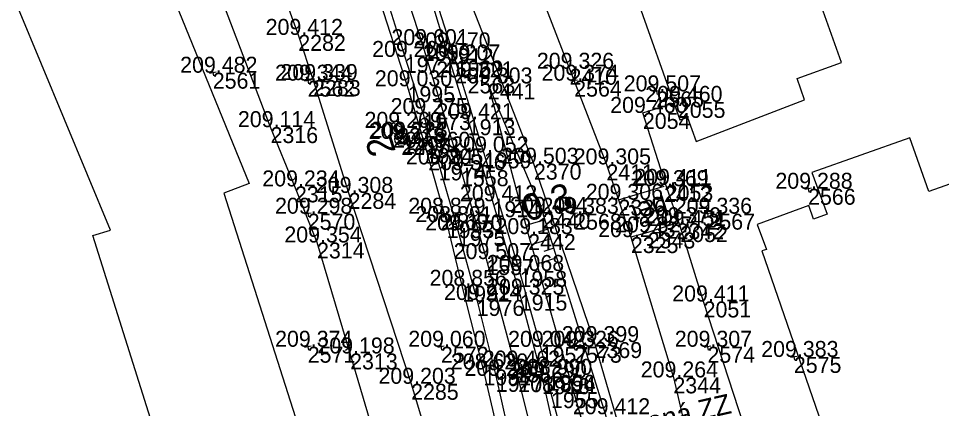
# Model space of a CAD drawing. Extents: x -556590 to -554855, y -1137918 to -1135717.
# Drawn here: x -555011.7 to -554942.4, y -1137304.6 to -1137275.3 of the extents above; entities that cross this region are included whole.
import ezdxf

# ---------------------------------------------------------------- set-up
doc = ezdxf.new("R2010")
doc.units = 0
for name, color, linetype in [('Vrstva 1', 7, 'Continuous'), ('Vrstva 11', 7, 'Continuous'), ('Vrstva 17', 7, 'Continuous'), ('Vrstva 23', 7, 'Continuous'), ('Vrstva 4', 7, 'Continuous'), ('Vrstva 48', 7, 'Continuous'), ('Vrstva 49', 7, 'Continuous'), ('Vrstva 50', 7, 'Continuous'), ('Vrstva 51', 7, 'Continuous'), ('Vrstva 60', 7, 'Continuous'), ('Vrstva 61', 7, 'Continuous'), ('Vrstva 7', 7, 'Continuous')]:
    doc.layers.add(name, color=color, linetype=linetype)

msp = doc.modelspace()

# ---------------------------------------------------------------- linework, layer by layer
at = {"layer": 'Vrstva 1'}
msp.add_lwpolyline([(-554957.769, -1137391.473), (-554957.969, -1137390.265), (-554958.079, -1137389.516), (-554959.228, -1137381.711), (-554960.83, -1137371.074), (-554962.414, -1137360.882), (-554964.146, -1137350.305), (-554965.833, -1137340.679), (-554967.766, -1137330.506), (-554969.82, -1137320.65), (-554972.001, -1137311.137), (-554974.412, -1137301.49), (-554976.593, -1137293.41), (-554978.496, -1137286.733), (-554981.36, -1137277.327), (-554984.2, -1137268.613)], dxfattribs=at)
at = {"layer": 'Vrstva 11'}
for p, q in [((-554982.974, -1137283.935), (-554983.78, -1137283.506)), ((-554982.791, -1137283.608), (-554983.609, -1137283.172)), ((-554983.466, -1137284.318), (-554982.648, -1137284.754)), ((-554983.283, -1137283.991), (-554982.477, -1137284.42))]:
    msp.add_line(p, q, dxfattribs=at)
for centre in [(-554983.284, -1137283.548), (-554982.973, -1137284.378)]:
    msp.add_circle(centre, 0.5, dxfattribs=at)
at = {"layer": 'Vrstva 17'}
msp.add_lwpolyline([(-554954.655, -1137315.2), (-554957.273, -1137305.896), (-554960.287, -1137296.596), (-554962.039, -1137290.931), (-554963.134, -1137287.835), (-554964.847, -1137282.426), (-554962.218, -1137281.595)], dxfattribs=at)
at = {"layer": 'Vrstva 23'}
for points in [[(-554974.008, -1137234.741), (-554973.079, -1137238.66), (-554969.088, -1137237.709), (-554968.749, -1137239.093), (-554976.722, -1137241.899), (-554973.235, -1137251.876), (-554974.414, -1137252.257), (-554966.688, -1137273.494), (-554965.541, -1137273.087), (-554962.076, -1137282.947), (-554961.502, -1137282.771), (-554960.834, -1137284.579), (-554952.711, -1137281.431), (-554953.254, -1137279.845), (-554949.927, -1137278.646), (-554953.433, -1137268.78), (-554952.345, -1137268.415), (-554960.023, -1137247.127), (-554960.935, -1137247.503), (-554964.348, -1137238.407), (-554963.788, -1137238.208), (-554965.053, -1137232.957), (-554974.008, -1137234.741)], [(-555001.443, -1137270.389), (-554994.396, -1137287.723), (-554996.287, -1137288.452), (-554990.752, -1137305.874), (-554993.395, -1137306.708), (-554992.699, -1137309.185), (-554997.164, -1137310.589), (-554997.913, -1137308.185), (-555000.641, -1137309.05), (-555006.14, -1137291.642), (-555004.803, -1137291.24), (-555011.71, -1137274.605), (-555001.443, -1137270.389)], [(-554956.269, -1137290.801), (-554955.577, -1137292.686), (-554955.907, -1137292.801), (-554949.985, -1137309.973), (-554932.082, -1137303.548), (-554938.146, -1137286.479), (-554943.374, -1137288.342), (-554944.804, -1137284.29), (-554952.158, -1137286.912), (-554951.004, -1137290.033), (-554952.049, -1137290.402), (-554952.396, -1137289.39), (-554956.269, -1137290.801)]]:
    msp.add_lwpolyline(points, dxfattribs=at)
at = {"layer": 'Vrstva 4'}
for points in [[(-554984.585, -1137272.161), (-554982.714, -1137278.214), (-554981.324, -1137282.511), (-554980.17, -1137286.294), (-554978.731, -1137291.261), (-554977.316, -1137296.485), (-554975.881, -1137302.19), (-554975.02, -1137305.996)], [(-554960.464, -1137357.894), (-554961.788, -1137349.985), (-554963.254, -1137342.035), (-554964.575, -1137334.605), (-554965.776, -1137328.563), (-554966.932, -1137323.165), (-554967.272, -1137321.836), (-554967.302, -1137321.017), (-554967.338, -1137320.155), (-554967.399, -1137319.362), (-554967.635, -1137318.37), (-554967.962, -1137317.497), (-554968.301, -1137316.757), (-554968.83, -1137314.749), (-554970.629, -1137307.661), (-554971.743, -1137303.413), (-554971.991, -1137302.111), (-554972.514, -1137300.008), (-554974.102, -1137294.303), (-554976.777, -1137285.388), (-554978.897, -1137278.481), (-554980.958, -1137272.034)], [(-554981.108, -1137272.667), (-554979.626, -1137277.571), (-554977.985, -1137282.899), (-554976.129, -1137289.063), (-554974.083, -1137296.082), (-554972.405, -1137302.364), (-554971.004, -1137308.524), (-554969.37, -1137314.887), (-554968.505, -1137317.978), (-554968.169, -1137318.756), (-554967.953, -1137319.386), (-554967.85, -1137320.101), (-554967.872, -1137320.992), (-554967.753, -1137322.155), (-554967.363, -1137323.728), (-554966.007, -1137329.874), (-554963.893, -1137340.445), (-554962.255, -1137349.518), (-554960.758, -1137358.397)], [(-554975.266, -1137308.383), (-554976.807, -1137301.701), (-554978.4, -1137295.42), (-554979.563, -1137290.636), (-554981.142, -1137285.042), (-554982.509, -1137280.423), (-554984.787, -1137273.316)]]:
    msp.add_lwpolyline(points, dxfattribs=at)
at = {"layer": 'Vrstva 48'}
for p, q in [((-554972.201, -1137290.451), (-554973.625, -1137290.894)), ((-554971.978, -1137291.167), (-554972.704, -1137291.393)), ((-554971.755, -1137291.884), (-554973.222, -1137292.34)), ((-554971.533, -1137292.6), (-554972.274, -1137292.83)), ((-554971.31, -1137293.316), (-554972.808, -1137293.782))]:
    msp.add_line(p, q, dxfattribs=at)
at = {"layer": 'Vrstva 49'}
for p, q in [((-554996.88, -1137279.355), (-554997.372, -1137279.449)), ((-554997.173, -1137279.156), (-554997.079, -1137279.648)), ((-554978.044, -1137279.509), (-554977.95, -1137280.001)), ((-554989.754, -1137279.953), (-554990.246, -1137280.047)), ((-554990.047, -1137279.754), (-554989.953, -1137280.246)), ((-554977.751, -1137279.708), (-554978.243, -1137279.802)), ((-554969.754, -1137279.953), (-554970.246, -1137280.047)), ((-554970.047, -1137279.754), (-554969.953, -1137280.246)), ((-554963.586, -1137280.756), (-554964.078, -1137280.85)), ((-554963.879, -1137280.557), (-554963.785, -1137281.049)), ((-554952.201, -1137288.079), (-554952.693, -1137288.173)), ((-554952.494, -1137287.88), (-554952.4, -1137288.372)), ((-554990.047, -1137289.754), (-554989.953, -1137290.246)), ((-554980.047, -1137289.754), (-554979.953, -1137290.246)), ((-554970.047, -1137289.754), (-554969.953, -1137290.246)), ((-554960.047, -1137289.754), (-554959.953, -1137290.246)), ((-554989.754, -1137289.953), (-554990.246, -1137290.047)), ((-554979.754, -1137289.953), (-554980.246, -1137290.047)), ((-554969.754, -1137289.953), (-554970.246, -1137290.047)), ((-554959.754, -1137289.953), (-554960.246, -1137290.047)), ((-554989.754, -1137299.953), (-554990.246, -1137300.047)), ((-554990.047, -1137299.754), (-554989.953, -1137300.246)), ((-554979.754, -1137299.953), (-554980.246, -1137300.047)), ((-554980.047, -1137299.754), (-554979.953, -1137300.246)), ((-554969.754, -1137299.953), (-554970.246, -1137300.047)), ((-554970.047, -1137299.754), (-554969.953, -1137300.246)), ((-554959.754, -1137299.953), (-554960.246, -1137300.047)), ((-554960.047, -1137299.754), (-554959.953, -1137300.246)), ((-554953.266, -1137300.721), (-554953.758, -1137300.815)), ((-554953.559, -1137300.522), (-554953.465, -1137301.014))]:
    msp.add_line(p, q, dxfattribs=at)
for points in [[(-554950.05, -1137381.227), (-554951.467, -1137375.494), (-554955.943, -1137353.724), (-554962.152, -1137325.032), (-554967.652, -1137305.072), (-554972.361, -1137289.937), (-554976.483, -1137280.207)], [(-554976.483, -1137280.207), (-554973.455, -1137291.531), (-554965.994, -1137317.481), (-554960.693, -1137339.64), (-554954.586, -1137370.859), (-554952.57, -1137378.325), (-554950.05, -1137381.227)]]:
    msp.add_lwpolyline(points, dxfattribs=at)
at = {"layer": 'Vrstva 51'}
for points in [[(-554945.281, -1137385.483), (-554946.86, -1137382.967), (-554948.848, -1137379.547), (-554950.193, -1137376.201), (-554951.497, -1137372.051), (-554952.924, -1137365.854), (-554955.055, -1137354.882), (-554957.461, -1137343.558), (-554960.398, -1137330.067), (-554964.003, -1137315.039), (-554968.471, -1137299.65), (-554973.022, -1137286.24), (-554979.752, -1137268.994), (-554986.923, -1137251.345), (-554989.226, -1137243.951), (-554990.077, -1137240.661), (-554990.818, -1137237.154), (-554990.968, -1137236.513)], [(-554975.898, -1137255.637), (-554977.07, -1137256.104), (-554978.157, -1137256.545), (-554979.058, -1137256.912), (-554974.217, -1137269.122), (-554970.351, -1137279.104), (-554967.582, -1137286.293), (-554966.681, -1137288.949), (-554965.745, -1137291.758), (-554962.557, -1137302.305), (-554959.814, -1137314.031), (-554956.963, -1137326.176), (-554954.222, -1137338.752), (-554951.618, -1137350.899), (-554949.32, -1137363.584), (-554948.201, -1137369.318), (-554947.085, -1137373.273), (-554945.53, -1137377.171), (-554943.889, -1137380.324), (-554941.879, -1137382.792), (-554945.281, -1137385.483)], [(-554992.243, -1137272.326), (-554990.709, -1137276.56), (-554989.594, -1137279.954), (-554986.932, -1137288.438), (-554982.239, -1137302.784), (-554977.503, -1137318.543), (-554975.16, -1137327.138), (-554972.624, -1137338.925), (-554970.76, -1137350.256), (-554970.002, -1137357.507), (-554969.708, -1137365.515), (-554970.03, -1137372.952), (-554971.29, -1137383.538), (-554972.956, -1137395.086), (-554974.603, -1137409.426), (-554975.926, -1137424.495), (-554976.695, -1137437.545), (-554977.147, -1137449.324)], [(-554990.63, -1137360.757), (-554986.061, -1137357.513), (-554982.918, -1137355.304), (-554981.153, -1137353.824), (-554979.47, -1137351.818), (-554977.899, -1137349.473), (-554976.839, -1137347.449), (-554976.197, -1137345.037), (-554976.109, -1137343.239), (-554976.396, -1137340.902), (-554977.828, -1137333.365), (-554979.78, -1137325.474), (-554982.165, -1137316.167), (-554983.7, -1137311.174), (-554984.68, -1137307.694), (-554986.819, -1137300.505), (-554989.303, -1137292.162), (-554990.959, -1137287.946), (-554992.789, -1137283.491), (-554996.889, -1137272.7)], [(-554966.681, -1137288.949), (-554963.255, -1137287.926)], [(-554962.313, -1137290.715), (-554964.482, -1137291.408), (-554965.745, -1137291.758)]]:
    msp.add_lwpolyline(points, dxfattribs=at)
at = {"layer": 'Vrstva 60'}
for p, q in [((-554990.709, -1137276.56), (-554990.709, -1137276.56)), ((-554981.36, -1137277.327), (-554981.36, -1137277.327)), ((-554979.626, -1137277.571), (-554979.626, -1137277.571)), ((-554982.714, -1137278.214), (-554982.714, -1137278.214)), ((-554978.897, -1137278.481), (-554978.897, -1137278.481)), ((-554997.126, -1137279.402), (-554997.126, -1137279.402)), ((-554970.351, -1137279.104), (-554970.351, -1137279.104)), ((-554990, -1137280), (-554990, -1137280)), ((-554989.594, -1137279.954), (-554989.594, -1137279.954)), ((-554977.997, -1137279.755), (-554977.997, -1137279.755)), ((-554976.483, -1137280.207), (-554976.483, -1137280.207)), ((-554970, -1137280), (-554970, -1137280)), ((-554982.509, -1137280.423), (-554982.509, -1137280.423)), ((-554963.832, -1137280.803), (-554963.832, -1137280.803)), ((-554962.218, -1137281.595), (-554962.218, -1137281.595)), ((-554981.324, -1137282.511), (-554981.324, -1137282.511)), ((-554977.985, -1137282.899), (-554977.985, -1137282.899)), ((-554964.847, -1137282.426), (-554964.847, -1137282.426)), ((-554992.789, -1137283.491), (-554992.789, -1137283.491)), ((-554983.284, -1137283.548), (-554983.284, -1137283.548)), ((-554982.842, -1137284.288), (-554982.842, -1137284.288)), ((-554982.973, -1137284.378), (-554982.973, -1137284.378)), ((-554981.142, -1137285.042), (-554981.142, -1137285.042)), ((-554976.777, -1137285.388), (-554976.777, -1137285.388)), ((-554980.17, -1137286.294), (-554980.17, -1137286.294)), ((-554973.022, -1137286.24), (-554973.022, -1137286.24)), ((-554967.582, -1137286.293), (-554967.582, -1137286.293)), ((-554978.496, -1137286.733), (-554978.496, -1137286.733)), ((-554963.134, -1137287.835), (-554963.134, -1137287.835)), ((-554990.959, -1137287.946), (-554990.959, -1137287.946)), ((-554986.932, -1137288.438), (-554986.932, -1137288.438)), ((-554963.255, -1137287.926), (-554963.255, -1137287.926)), ((-554952.447, -1137288.126), (-554952.447, -1137288.126)), ((-554976.129, -1137289.063), (-554976.129, -1137289.063)), ((-554966.681, -1137288.949), (-554966.681, -1137288.949)), ((-554990, -1137290), (-554990, -1137290)), ((-554980, -1137290), (-554980, -1137290)), ((-554972.361, -1137289.937), (-554972.361, -1137289.937)), ((-554970, -1137290), (-554970, -1137290)), ((-554960, -1137290), (-554960, -1137290)), ((-554979.563, -1137290.636), (-554979.563, -1137290.636)), ((-554978.731, -1137291.261), (-554978.731, -1137291.261)), ((-554962.313, -1137290.715), (-554962.313, -1137290.715)), ((-554962.039, -1137290.931), (-554962.039, -1137290.931)), ((-554973.455, -1137291.531), (-554973.455, -1137291.531)), ((-554965.745, -1137291.758), (-554965.745, -1137291.758)), ((-554964.482, -1137291.408), (-554964.482, -1137291.408)), ((-554989.303, -1137292.162), (-554989.303, -1137292.162)), ((-554976.593, -1137293.41), (-554976.593, -1137293.41)), ((-554974.102, -1137294.303), (-554974.102, -1137294.303)), ((-554978.4, -1137295.42), (-554978.4, -1137295.42)), ((-554974.083, -1137296.082), (-554974.083, -1137296.082)), ((-554977.316, -1137296.485), (-554977.316, -1137296.485)), ((-554960.287, -1137296.596), (-554960.287, -1137296.596)), ((-554990, -1137300), (-554990, -1137300)), ((-554980, -1137300), (-554980, -1137300)), ((-554972.514, -1137300.008), (-554972.514, -1137300.008)), ((-554970, -1137300), (-554970, -1137300)), ((-554968.471, -1137299.65), (-554968.471, -1137299.65)), ((-554960, -1137300), (-554960, -1137300)), ((-554986.819, -1137300.505), (-554986.819, -1137300.505)), ((-554953.512, -1137300.768), (-554953.512, -1137300.768)), ((-554974.412, -1137301.49), (-554974.412, -1137301.49)), ((-554976.807, -1137301.701), (-554976.807, -1137301.701)), ((-554975.881, -1137302.19), (-554975.881, -1137302.19)), ((-554972.405, -1137302.364), (-554972.405, -1137302.364)), ((-554971.991, -1137302.111), (-554971.991, -1137302.111)), ((-554962.557, -1137302.305), (-554962.557, -1137302.305)), ((-554982.239, -1137302.784), (-554982.239, -1137302.784)), ((-554971.743, -1137303.413), (-554971.743, -1137303.413))]:
    msp.add_line(p, q, dxfattribs=at)
at = {"layer": 'Vrstva 7'}
for p, q in [((-554982.363, -1137284.143), (-554983.321, -1137284.433)), ((-554982.987, -1137283.809), (-554982.697, -1137284.767))]:
    msp.add_line(p, q, dxfattribs=at)

# ---------------------------------------------------------------- texts
at = {"layer": 'Vrstva 11'}
msp.add_text('2', height=2, rotation=106.93478, dxfattribs=at).set_placement((-554983.373, -1137285.324))
at = {"layer": 'Vrstva 48'}
msp.add_text('0,3', height=2, rotation=17.28265, dxfattribs=at).set_placement((-554973.526, -1137290.634))
at = {"layer": 'Vrstva 50'}
msp.add_text('poškozená ZZ', height=1.5, rotation=12.78812, dxfattribs=at).set_placement((-554970.507, -1137307.791))
at = {"layer": 'Vrstva 51'}
msp.add_text('bet.', height=1.5, rotation=197.71879, dxfattribs=at).set_placement((-554963.258, -1137288.564))
at = {"layer": 'Vrstva 60'}
for s, p in [('2282', (-554990.709, -1137277.76)), ('1559', (-554981.36, -1137278.527)), ('1912', (-554979.626, -1137278.771)), ('1972', (-554982.714, -1137279.414)), ('1960', (-554978.897, -1137279.681)), ('2561', (-554997.126, -1137280.602)), ('2410', (-554970.351, -1137280.304)), ('2562', (-554990, -1137281.2)), ('2283', (-554989.594, -1137281.154)), ('2563', (-554977.997, -1137280.955)), ('2441', (-554976.483, -1137281.407)), ('2564', (-554970, -1137281.2)), ('1995', (-554982.509, -1137281.623)), ('2565', (-554963.832, -1137282.003)), ('2055', (-554962.218, -1137282.795)), ('1973', (-554981.324, -1137283.711)), ('1913', (-554977.985, -1137284.099)), ('2054', (-554964.847, -1137283.626)), ('2316', (-554992.789, -1137284.691)), ('2218', (-554983.284, -1137284.748)), ('2217', (-554982.973, -1137285.578)), ('1495', (-554982.842, -1137285.488)), ('1994', (-554981.142, -1137286.242)), ('1959', (-554976.777, -1137286.588)), ('1974', (-554980.17, -1137287.494)), ('2370', (-554973.022, -1137287.44)), ('2411', (-554967.582, -1137287.493)), ('1558', (-554978.496, -1137287.933)), ('2053', (-554963.134, -1137289.035)), ('2315', (-554990.959, -1137289.146)), ('2284', (-554986.932, -1137289.638)), ('2412', (-554963.255, -1137289.126)), ('2566', (-554952.447, -1137289.326)), ('1914', (-554976.129, -1137290.263)), ('2326', (-554966.681, -1137290.149)), ('2570', (-554990, -1137291.2)), ('2569', (-554980, -1137291.2)), ('2440', (-554972.361, -1137291.137)), ('2568', (-554970, -1137291.2)), ('2567', (-554960, -1137291.2)), ('1993', (-554979.563, -1137291.836)), ('1975', (-554978.731, -1137292.461)), ('2342', (-554962.313, -1137291.915)), ('2052', (-554962.039, -1137292.131)), ('2442', (-554973.455, -1137292.731)), ('2325', (-554965.745, -1137292.958)), ('2343', (-554964.482, -1137292.608)), ('2314', (-554989.303, -1137293.362)), ('1557', (-554976.593, -1137294.61)), ('1958', (-554974.102, -1137295.503)), ('1992', (-554978.4, -1137296.62)), ('1915', (-554974.083, -1137297.282)), ('1976', (-554977.316, -1137297.685)), ('2051', (-554960.287, -1137297.796)), ('2571', (-554990, -1137301.2)), ('2572', (-554980, -1137301.2)), ('1957', (-554972.514, -1137301.208)), ('2573', (-554970, -1137301.2)), ('2369', (-554968.471, -1137300.85)), ('2574', (-554960, -1137301.2)), ('2313', (-554986.819, -1137301.705)), ('2575', (-554953.512, -1137301.968)), ('1991', (-554976.807, -1137302.901)), ('1556', (-554974.412, -1137302.69)), ('1977', (-554975.881, -1137303.39)), ('1916', (-554972.405, -1137303.564)), ('1956', (-554971.991, -1137303.311)), ('2344', (-554962.557, -1137303.505)), ('2285', (-554982.239, -1137303.984)), ('1955', (-554971.743, -1137304.613))]:
    msp.add_text(s, height=1.2, dxfattribs=at).set_placement(p)
at = {"layer": 'Vrstva 61'}
for s, p in [('209.412', (-554993.157, -1137276.56)), ('209.601', (-554983.717, -1137277.327)), ('209.470', (-554982.077, -1137277.571)), ('209.266', (-554985.166, -1137278.214)), ('209.207', (-554981.349, -1137278.481)), ('209.326', (-554972.803, -1137279.104)), ('209.482', (-554999.574, -1137279.402)), ('209.344', (-554992.451, -1137280)), ('209.339', (-554992.048, -1137279.954)), ('209.221', (-554980.354, -1137279.755)), ('209.374', (-554972.451, -1137280)), ('209.030', (-554984.96, -1137280.423)), ('209.303', (-554978.935, -1137280.207)), ('209.507', (-554966.284, -1137280.803)), ('209.460', (-554964.669, -1137281.595)), ('209.275', (-554983.78, -1137282.511)), ('209.460', (-554967.298, -1137282.426)), ('209.114', (-554995.24, -1137283.491)), ('209.421', (-554980.342, -1137282.899)), ('209.269', (-554985.738, -1137283.548)), ('209.274', (-554985.424, -1137284.378)), ('209.723', (-554985.294, -1137284.288)), ('208.960', (-554983.593, -1137285.042)), ('209.052', (-554979.225, -1137285.388)), ('209.503', (-554975.474, -1137286.24)), ('209.205', (-554982.626, -1137286.294)), ('209.546', (-554980.948, -1137286.733)), ('209.305', (-554970.038, -1137286.293)), ('209.234', (-554993.41, -1137287.946)), ('209.369', (-554965.709, -1137287.926)), ('209.411', (-554965.491, -1137287.835)), ('209.288', (-554954.901, -1137288.126)), ('209.308', (-554989.386, -1137288.438)), ('209.306', (-554969.133, -1137288.949)), ('209.412', (-554978.577, -1137289.063)), ('209.298', (-554992.454, -1137290)), ('208.879', (-554982.454, -1137290)), ('209.494', (-554974.812, -1137289.937)), ('209.383', (-554972.452, -1137290)), ('209.336', (-554962.452, -1137290)), ('208.891', (-554981.92, -1137290.636)), ('209.379', (-554964.767, -1137290.715)), ('209.451', (-554964.396, -1137290.931)), ('209.170', (-554981.182, -1137291.261)), ('209.183', (-554975.907, -1137291.531)), ('209.243', (-554968.197, -1137291.758)), ('209.327', (-554966.934, -1137291.408)), ('209.354', (-554991.754, -1137292.162)), ('209.507', (-554979.045, -1137293.41)), ('209.068', (-554976.556, -1137294.303)), ('208.856', (-554980.852, -1137295.42)), ('209.214', (-554979.767, -1137296.485)), ('209.325', (-554976.539, -1137296.082)), ('209.411', (-554962.644, -1137296.596)), ('209.374', (-554992.451, -1137300)), ('209.060', (-554982.451, -1137300)), ('209.042', (-554974.962, -1137300.008)), ('209.326', (-554972.452, -1137300)), ('209.399', (-554970.925, -1137299.65)), ('209.307', (-554962.452, -1137300)), ('209.198', (-554989.273, -1137300.505)), ('209.383', (-554955.964, -1137300.768)), ('209.462', (-554976.86, -1137301.49)), ('208.620', (-554979.258, -1137301.701)), ('209.231', (-554978.238, -1137302.19)), ('208.990', (-554974.442, -1137302.111)), ('209.203', (-554984.691, -1137302.784)), ('209.290', (-554974.856, -1137302.364)), ('209.264', (-554965.008, -1137302.305)), ('208.894', (-554974.194, -1137303.413)), ('209.412', (-554970.1, -1137305.072))]:
    msp.add_text(s, height=1.2, dxfattribs=at).set_placement(p)

doc.saveas('drawing.dxf')
